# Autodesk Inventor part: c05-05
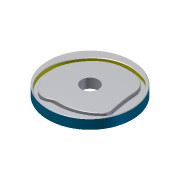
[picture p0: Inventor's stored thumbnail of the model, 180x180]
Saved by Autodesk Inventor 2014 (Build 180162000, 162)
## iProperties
Created: 2010-11
Part Number: c05-05
Material: Generic
Document SubType Name: Modeling
Designer: Thom Tremblay
Density: 1 g/cm^3
Appearance: Aluminum - Flat
Author: Thom Tremblay
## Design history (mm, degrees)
sketch "Sketch1"
  geometry: L1 (0, 0)-(-60.5, 0); C1 r 87.5 at (0, 0); A1 r 101.47 centre (31.646, -25.639) between (-38.097, 48.063) and (-62.849, 11.331); A2 r 69.237 centre (9.492, -2.228) between (26.447, 64.902) and (-38.097, 48.063); A3 r 616.928 centre (177.52, 663.047) between (26.447, 64.902) and (36.513, 62.449); A4 r 31.238 centre (29.374, 32.038) between (60.537, 34.197) and (36.513, 62.449); A5 r 355.938 centre (415.623, 58.803) between (60.537, 34.197) and (69.16, -22.773); A6 r 16.738 centre (52.867, -26.609) between (64.611, -38.536) and (69.16, -22.773); A7 r 90.559 centre (1.073, 25.992) between (-3.077, -64.472) and (64.611, -38.536); A8 r 22.685 centre (-4.116, -87.133) between (-3.077, -64.472) and (-15.476, -67.497); A9 r 23.983 centre (-27.486, -46.739) between (-42.594, -65.365) and (-15.476, -67.497); A10 r 67.218 centre (-0.251, -13.16) between (-62.849, 11.331) and (-42.594, -65.365); A11 r 609.928 centre (177.52, 663.047) between (28.161, 71.689) and (38.113, 69.264); A12 r 76.237 centre (9.492, -2.228) between (28.161, 71.689) and (-42.908, 53.147); A13 r 108.47 centre (31.646, -25.639) between (-42.908, 53.147) and (-69.368, 13.882); A14 r 74.218 centre (-0.251, -13.16) between (-69.368, 13.882) and (-47.003, -70.802); A15 r 30.983 centre (-27.486, -46.739) between (-47.003, -70.802) and (-11.971, -73.557); A16 r 15.685 centre (-4.116, -87.133) between (-3.398, -71.465) and (-11.971, -73.557); A17 r 97.559 centre (1.073, 25.992) between (-3.398, -71.465) and (69.522, -43.524); A18 r 23.738 centre (52.867, -26.609) between (69.522, -43.524) and (75.973, -21.169); A19 r 348.938 centre (415.623, 58.803) between (67.52, 34.681) and (75.973, -21.169); A20 r 38.238 centre (29.374, 32.038) between (67.52, 34.681) and (38.113, 69.264); 1 further point
  constraints: 40 point on circle, 21 centre point, 10 tangent, 2 coincident, 2 end point, 1 horizontal, 1 horizontal alignment, 11 other
  dimensions: "d19" = 175 diameter of C1; "d23" = 27 dimension on C1; "d24" = 7 radial gap between concentric circles of A20 A4
sketch "Sketch2"
  geometry: C1 r 17.5 at (0, 0); C2 r 87.5 at (0, 0); 1 further point
  constraints: 2 centre point, 2 coincident
  dimensions: "d13" = 35 diameter of C1; "d14" = 175 diameter of C2
extrude "Extrusion2" new body sketch "Sketch2" distance "d15" = 20; taper "d16" = 0 deg
extrude "Extrusion3" cut sketch "Sketch1" distance "d17" = 8; taper "d18" = 0 deg
chamfer "Chamfer1" distance "d20" = 1; stored, may be unused: second distance "d21" = 2, angle "d22" = 45 deg
body "Solid2"
